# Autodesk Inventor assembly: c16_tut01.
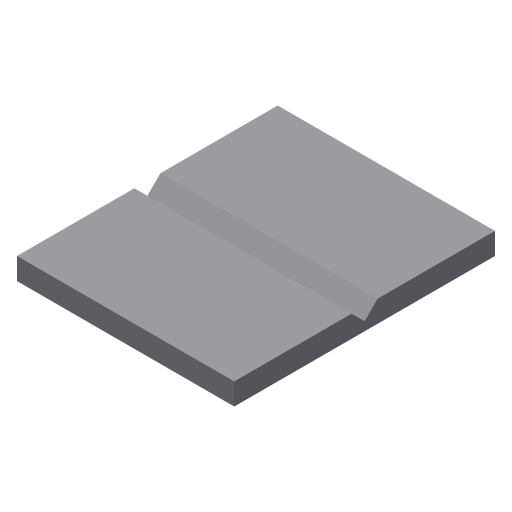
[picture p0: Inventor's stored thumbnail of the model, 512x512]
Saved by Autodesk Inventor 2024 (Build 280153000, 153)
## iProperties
Created: 2010-05
Part Number: c16_tut01.
Document SubType Name: Weldment
Designer: CADSoft
Weld Material: Welded Aluminum-6061
Author: CADSoft
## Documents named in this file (2)
- D:\PROJECTS\Project 2023\RESOURCES INVENTOR 2024\RESOURCES INVENTOR 2024\Inventor_2024_tut\Inventor_2024_tut\c16_Inv_2024_tut\c16_Inv_tut_2024\c16_tut01\c16_tut01..iam
- D:\PROJECTS\Project 2023\RESOURCES INVENTOR 2024\RESOURCES INVENTOR 2024\Inventor_2024_tut\Inventor_2024_tut\c16_Inv_2024_tut\c16_Inv_tut_2024\c16_tut01\Plate..ipt
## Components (2 placed, 1 different names)
1. Plate.:1 — Mate:1, Flush:1, Flush:2
2. Plate.:2 — Mate:1, Flush:1, Flush:2
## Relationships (3: Flush 2, Mate 1)
- Mate:1: Plate.:1 ↔ Plate.:2
- Flush:1: Plate.:1 ↔ Plate.:2
- Flush:2: Plate.:1 ↔ Plate.:2
